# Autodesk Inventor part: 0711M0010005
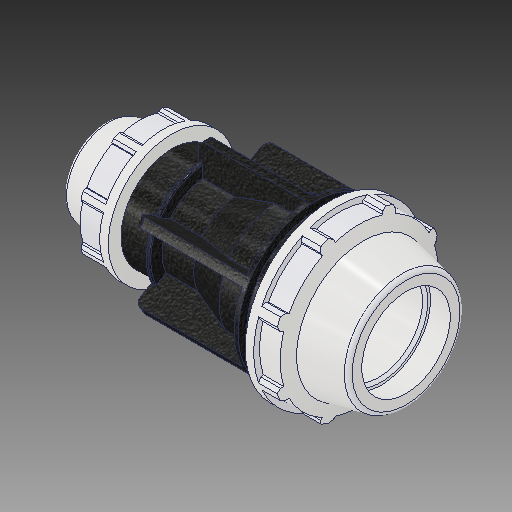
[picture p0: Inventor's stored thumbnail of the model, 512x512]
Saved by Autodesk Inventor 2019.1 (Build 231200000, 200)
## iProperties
Created: 2017-02
Part Number: 0711M0010005
Material: PVC-Piping
Description: PLASSON REDUCING COUPLER 1'' - 1/2''
Document SubType Name: Modeling
Designer: KIM
Mass: 92.6774 g
Surface Area: 199.44 cm^2
Volume: 66.1981 cm^3
Density: 1.4 g/cm^3
Appearance: PTFE
Author: KIM
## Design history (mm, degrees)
derived "0711M0.ipt"
feature "Solid1::0711M0.ipt"
tag "TaggingFeature1"
body "Solid1"
other parameters: "d2" = 33.3, "d4" = 9.41667, "d5" = 16.14286, "d7" = 64.008, "d9" = 16.14286, "d11" = 1.61429, "d12" = 51.2064, "d13" = 120 deg, "d14" = 43.29, "d15" = 12 deg, "d16" = 57.6072, "d18" = 1.665, "d19" = 35 deg, "d20" = 17.5 deg, "d21" = 59.52744, "d23" = 0, "d25" = 360 deg, "d27" = 1.28016, "d42" = 12.43, "d46" = 0.999, "d51" = 113, "d52" = 38.96552, "d53" = 12 deg, "d54" = 48.006, "d56" = 31.8, "d57" = 21.2, "d58" = 29.97, "d59" = 19.08, "d60" = 43.2054, "d61" = 38.4048, "d62" = 11.3, "d63" = 13.56, "d64" = 120 deg, "d65" = 48.006, "d68" = 8.07143, "d74" = 44.64558, "d75" = 35 deg, "d76" = 17.5 deg, "d78" = 0, "d80" = 360 deg, "d85" = 0.96012, "d88" = 0.424, "d94" = 44.8056, "d97" = 2.11927, "d98" = 3.2004, "d99" = 0, "d100" = 2.56032, "d102" = 360 deg, "d104" = 2, "d106" = 0, "d107" = 3.2004, "d108" = 0, "d109" = 3.2004, "d110" = 0, "d_" = 33.3, "E_" = 64.008, "H_" = 113, "l_" = 48.006, "d_1" = 21.2, "E_1" = 48.006, "d96" = 6.3578
